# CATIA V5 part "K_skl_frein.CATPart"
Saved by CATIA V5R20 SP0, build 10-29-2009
Part number: skl_frein
Publications: "Axe_frein_arriere"
Bounding box of the stored display mesh (mm): x -20 to 20, y 700 to 770.711, z 0 to 70.711
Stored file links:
  G:\Khaled_CFAO_2011\SIL\SIL_GR2\ahabrial\ahabrial\Khaled\CAD_ThinkMOTION\K_skl_frein.CATPart
  G:\Données\Ecole\IFMA\2A\Thinkmotion2\Etape18\trotinette.CATProduct
  G:\Khaled_CFAO_2011\SIL\SIL_GR2\ahabrial\ahabrial\Khaled\CAD_ThinkMOTION\K_skl_avant.CATPart
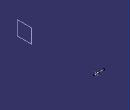
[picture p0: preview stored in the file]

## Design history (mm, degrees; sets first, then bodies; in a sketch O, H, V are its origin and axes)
Set1
  Point1: linked copy from another document
  Plane1 "Plan_ref": linked copy from another document
Body1 (main body)
  Line1 "Droite_frein": type PtDir, RefPoint Point1, Direction (0, 10, 10), Start 0, End 100
  Line2 "Axe_frein_arriere": type Normal, RefPoint Point1, RefSkin Plane1, Start -20, End 20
